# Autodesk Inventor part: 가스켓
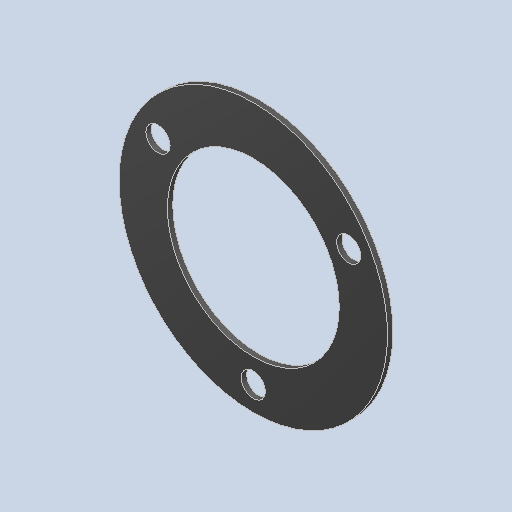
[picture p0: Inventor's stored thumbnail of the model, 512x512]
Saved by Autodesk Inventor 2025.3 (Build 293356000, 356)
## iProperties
Created: 2025-10
Part Number: 가스켓
Material: 스테인리스스틸
Document SubType Name: Modeling
Designer: USER
Density: 8 g/cm^3
Appearance: 기본값
Author: jhkim
Sending System: Autodesk Inventor 2026
Preprocessor: ST-DEVELOPER v20.1
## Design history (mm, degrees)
feature "솔리드1"
node "솔리드2"
